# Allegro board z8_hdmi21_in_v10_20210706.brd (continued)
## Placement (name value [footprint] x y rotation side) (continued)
R275  49.9R  [R0402]  21.59 35.12 180 top
R276  49.9R  [R0402]  21.59 33.59 180 top
R277  49.9R  [R0402]  24.51 33.46 180 top
R278  49.9R  [R0402]  24.51 31.94 180 top
R279  49.9R  [R0402]  21.59 31.81 180 top
R280  49.9R  [R0402]  21.59 30.29 180 top
R281  49.9R  [R0402]  24.51 30.16 180 top
R282  49.9R  [R0402]  24.51 28.64 180 top
R283  49.9K  [R0402]  168.02 27.37 90 top
R284  49.9K  [R0402]  208.28 27.37 270 top
R285  200K  [R0402]  209.42 27.37 270 top
R286  0R  [R0402]  35.05 25.97 180 top
R287  0R  [R0402]  37.47 25.97 0 top
R288  0R_NC  [R0402]  29.84 25.46 90 top
R289  0R_NC  [R0402]  30.99 25.46 90 top
R290  500K  [R0402]  33.27 25.46 270 top
R291  100K  [R0402]  168.02 24.96 90 top
R292  2K  [R0402]  46.99 24.57 270 top
R293  3  [R0402]  157.23 24.19 90 top
R294  0R_NC  [R0402]  35.56 24.19 270 top
R295  0R_NC  [R0402]  36.96 24.19 270 top
R296  47K  [R0402]  38.99 24.19 180 top
R297  47K  [R0402]  29.21 23.69 180 top
R298  47K  [R0402]  31.62 23.69 0 top
R299  47K  [R0402]  38.96 22.92 180 top
R300  2K  [R0402]  46.99 22.29 90 top
R301  0R  [R0402]  29.72 21.91 270 top
R302  0R  [R0402]  31.12 21.91 270 top
R303  200K  [R0402]  38.96 20.51 180 top
R304  147K  [R0402]  64.52 19.24 180 top
R305  100K  [R0402]  91.19 19.24 180 top
R306  20K  [R0402]  110.11 19.24 180 top
R307  200K  [R0402]  176.91 19.24 180 top
R308  20K  [R0402]  66.29 18.73 90 top
R309  49.9K  [R0402]  70.74 18.73 270 top
R310  100K  [R0402]  92.96 18.73 90 top
R311  49.9K  [R0402]  97.41 18.73 270 top
R312  28K  [R0402]  111.89 18.73 90 top
R313  49.9K  [R0402]  116.33 18.73 270 top
R314  100K  [R0402]  178.69 18.73 90 top
R315  49.9K  [R0402]  183.13 18.73 270 top
R316  300  [R0402]  14.99 17.34 180 top
R317  52.3K  [R0402]  70.74 16.45 270 top
R318  52.3K  [R0402]  97.41 16.45 270 top
R319  52.3K  [R0402]  116.33 16.45 270 top
R320  52.3K  [R0402]  183.13 16.45 270 top
R321  10K  [R0402]  68.96 15.94 180 top
R322  10K  [R0402]  95.63 15.94 180 top
R323  10K  [R0402]  114.55 15.94 180 top
R324  10K  [R0402]  181.36 15.94 180 top
R325  300  [R0402]  14.99 15.81 180 top
R326  300  [R0402]  14.99 11.11 180 top
R327  300  [R0402]  14.99 9.59 180 top
R328  1M  [R0402]  96.39 7.18 180 top
R329  1M  [R0402]  147.19 7.18 180 top
R330  1M  [R0402]  197.99 7.18 180 top
R335  1K-NC  [R0402]  44.96 149.8 0 bottom
R336  1K-NC  [R0402]  44.96 148.53 0 bottom
R337  1K-NC  [R0402]  44.96 147.39 0 bottom
R338  1K-NC  [R0402]  27.81 146.76 0 bottom
R339  1K  [R0402]  25.53 146.76 180 bottom
R340  1K-NC  [R0402]  44.96 146.12 0 bottom
R341  1K  [R0402]  27.81 145.49 0 bottom
R342  1K-NC  [R0402]  25.53 145.49 180 bottom
R343  10K-NC  [R0402]  44.96 144.85 0 bottom
R344  10K-NC  [R0402]  27.81 143.84 0 bottom
R345  1K-NC  [R0402]  25.53 143.84 180 bottom
R346  10K-NC  [R0402]  44.96 143.57 0 bottom
R347  10K-NC  [R0402]  27.81 142.57 0 bottom
R348  1K-NC  [R0402]  25.53 142.57 180 bottom
R349  10K  [R0402]  44.96 142.44 0 bottom
R350  1K  [R0402]  27.81 141.3 0 bottom
R351  1K-NC  [R0402]  25.53 141.3 180 bottom
R352  1K-NC  [R0402]  44.96 141.17 0 bottom
R353  50  [R0402]  142.49 140.78 270 bottom
R354  50  [R0402]  141.35 140.78 270 bottom
R355  50  [R0402]  140.21 140.78 270 bottom
R356  50  [R0402]  139.06 140.78 270 bottom
R357  50  [R0402]  137.92 140.78 270 bottom
R358  50  [R0402]  136.78 140.78 270 bottom
R359  50  [R0402]  135.64 140.78 270 bottom
R360  50  [R0402]  134.49 140.78 270 bottom
R361  50  [R0402]  133.35 140.78 270 bottom
R362  50  [R0402]  132.21 140.78 270 bottom
R363  50  [R0402]  131.06 140.78 270 bottom
R364  50  [R0402]  129.92 140.78 270 bottom
R365  50  [R0402]  128.78 140.78 270 bottom
R366  50  [R0402]  127.64 140.78 270 bottom
R367  1K-NC  [R0402]  44.96 140.03 0 bottom
R368  1K  [R0402]  27.81 140.03 0 bottom
R369  1K-NC  [R0402]  25.53 140.03 180 bottom
R370  1K-NC  [R0402]  44.96 138.76 0 bottom
R371  1K  [R0402]  27.81 138.76 0 bottom
R372  1K-NC  [R0402]  25.53 138.76 180 bottom
R373  1K-NC  [R0402]  44.96 137.61 0 bottom
R380  100  [R0402]  134.87 131.03 270 bottom
R381  65K_NC  [R0402]  38.86 118.55 270 bottom
R382  65K  [R0402]  37.97 116.52 180 bottom
R383  65K_NC  [R0402]  29.72 116.52 0 bottom
R384  65K  [R0402]  27.43 116.52 0 bottom
R385  0R-NC  [R0402]  27.3 115.38 180 bottom
R386  0R  [R0402]  40.01 114.62 270 bottom
R387  0R-NC  [R0402]  38.86 114.62 270 bottom
R388  0R-NC  [R0402]  27.3 114.24 180 bottom
R389  65K_NC  [R0402]  37.21 113.22 90 bottom
R390  50  [R0402]  181.74 112.97 180 bottom
R391  65K_NC  [R0402]  39.5 112.71 180 bottom
R392  65K_NC  [R0402]  29.72 111.95 0 bottom
R393  65K_NC  [R0402]  27.3 111.95 0 bottom
R394  50  [R0402]  181.74 111.82 180 bottom
R395  50  [R0402]  181.74 110.68 180 bottom
R396  2K  [C0402-8]  121.88 109.62 0 bottom
R397  50  [R0402]  181.74 109.54 180 bottom
R398  10K  [C0402-8]  138.88 108.62 180 bottom
R399  50  [R0402]  181.74 108.39 180 bottom
R400  1K  [R0402]  140.59 108.14 90 bottom
R401  10K  [C0402-8]  138.88 107.62 180 bottom
R402  50  [R0402]  181.74 107.25 180 bottom
R403  240  [C0402-8]  144.39 106.12 90 bottom
R404  50  [R0402]  181.74 106.11 180 bottom
R405  100  [R0402]  171.98 105.6 180 bottom
R406  10K  [R0402]  145.54 143.95 90 bottom
R407  50  [R0402]  181.74 104.97 180 bottom
R408  4.7K/NC  [R0402]  132.08 104.97 270 bottom
R409  4.7K  [R0402]  130.94 104.97 270 bottom
R410  0-NC  [R0402]  136.91 104.46 90 bottom
R411  50  [R0402]  181.74 103.82 180 bottom
R412  0  [R0402]  135.76 103.7 90 bottom
R413  0  [C0402-8]  138.88 103.62 180 bottom
R414  0  [C0402-8]  140.39 103.12 90 bottom
R415  50  [R0402]  181.74 102.68 180 bottom
R416  4.7K/NC  [R0402]  132.08 102.68 90 bottom
R417  4.7K  [R0402]  130.94 102.68 90 bottom
R418  1K  [C0402-8]  137.89 102.62 180 bottom
R419  50  [R0402]  181.74 101.54 180 bottom
R420  10K  [C0402-8]  138.39 101.12 270 bottom
R421  0  [R0402]  134.75 100.9 0 bottom
R422  1K-NC  [R0402]  132.46 100.9 180 bottom
R423  50  [R0402]  181.74 100.39 180 bottom
R424  50  [R0402]  181.74 99.25 180 bottom
R425  0-NC  [C0402-8]  135.39 99.12 90 bottom
R426  50  [R0402]  181.74 98.11 180 bottom
R427  10K  [C0402-8]  122.89 96.62 0 bottom
R428  50  [R0402]  181.74 96.33 180 bottom
R429  0-NC  [C0402-8]  132.39 96.12 90 bottom
R430  50  [R0402]  181.74 95.19 180 bottom
R431  50  [R0402]  181.74 94.04 180 bottom
R432  50  [R0402]  181.74 92.9 180 bottom
R433  50  [R0402]  181.74 91.76 180 bottom
R434  10K  [C0402-8]  122.89 91.62 0 bottom
R435  50  [R0402]  181.74 90.61 180 bottom
R436  65K_NC  [R0402]  38.86 90.61 270 bottom
R437  100  [R0402]  171.98 89.85 180 bottom
R438  50  [R0402]  181.74 89.47 180 bottom
R439  65K  [R0402]  37.97 88.58 180 bottom
R440  65K_NC  [R0402]  29.72 88.58 0 bottom
R441  65K  [R0402]  27.43 88.58 0 bottom
R442  50  [R0402]  181.74 88.33 180 bottom
R443  10K  [C0402-8]  123.89 87.62 180 bottom
R444  0R-NC  [R0402]  27.3 87.44 180 bottom
R445  50  [R0402]  181.74 87.19 180 bottom
R446  0R  [R0402]  40.01 86.68 270 bottom
R447  0R-NC  [R0402]  38.86 86.68 270 bottom
R448  0R-NC  [R0402]  27.3 86.3 180 bottom
R449  50  [R0402]  181.74 86.04 180 bottom
R450  65K_NC  [R0402]  37.21 85.28 90 bottom
R451  50  [R0402]  181.74 84.9 180 bottom
R452  65K_NC  [R0402]  39.5 84.77 180 bottom
R453  240  [C0402-8]  143.39 84.11 270 bottom
R454  65K_NC  [R0402]  29.72 84.01 0 bottom
R455  65K_NC  [R0402]  27.43 84.01 0 bottom
R456  50  [R0402]  181.74 83.76 180 bottom
R457  240  [C0402-8]  125.39 83.13 90 bottom
R458  50  [R0402]  181.74 82.61 180 bottom
R459  50  [R0402]  181.74 81.47 180 bottom
R460  0  [C0402-8]  138.39 77.13 90 bottom
R461  2K  [C0402-8]  122.84 76.61 180 bottom
R462  65K_NC  [R0402]  38.86 62.67 270 bottom
R463  65K  [R0402]  37.97 60.64 180 bottom
R464  65K_NC  [R0402]  29.72 60.64 0 bottom
R465  65K  [R0402]  27.43 60.64 0 bottom
R466  0R-NC  [R0402]  27.3 59.5 180 bottom
R467  0R  [R0402]  40.01 58.74 270 bottom
R468  0R-NC  [R0402]  38.86 58.74 270 bottom
R469  0R-NC  [R0402]  27.3 58.36 180 bottom
R470  65K_NC  [R0402]  37.21 57.34 90 bottom
R471  65K_NC  [R0402]  39.5 56.83 180 bottom
R472  65K_NC  [R0402]  29.72 56.07 0 bottom
R473  65K_NC  [R0402]  27.3 56.07 0 bottom
R474  10K  [R0402]  219.96 51.5 0 bottom
R475  65K_NC  [R0402]  38.86 34.73 270 bottom
R476  65K  [R0402]  37.97 32.7 180 bottom
R477  65K_NC  [R0402]  29.72 32.7 0 bottom
R478  65K  [R0402]  27.43 32.7 0 bottom
R479  0R-NC  [R0402]  27.3 31.56 180 bottom
R480  0R  [R0402]  40.01 30.8 270 bottom
R481  0R-NC  [R0402]  38.86 30.8 270 bottom
R482  0R-NC  [R0402]  27.3 30.42 180 bottom
R483  14.7K  [R0402]  166.75 29.53 180 bottom
R484  65K_NC  [R0402]  37.21 29.4 90 bottom
R485  65K_NC  [R0402]  39.5 28.89 180 bottom
R486  65K_NC  [R0402]  29.72 28.13 0 bottom
R487  65K_NC  [R0402]  27.3 28.13 0 bottom
R488  100K  [R0402]  166.75 27.75 180 bottom
R489  2  [R0402]  164.97 26.48 270 bottom
R490  200K  [R0402]  169.55 20.38 90 bottom
R491  147K  [R0402]  168.4 20.38 90 bottom
R492  187K-NC  [R0402]  166.75 20.38 90 bottom
R493  0-NC  [R0402]  166.75 18.1 270 bottom
R691  22R  [R0402]  215.16 56.5 270 top
R693  22R  [R0402]  214.02 56.5 270 top
R694  22R  [R0402]  211.73 56.5 270 top
R695  22R  [R0402]  212.88 56.5 270 top
R696  22R  [R0402]  214.5 42.61 90 top
R697  22R  [R0402]  216.84 42.58 90 top
R698  22R  [R0402]  215.67 42.58 90 top
R699  22R  [R0402]  148.08 143.95 90 bottom
R700  22R  [R0402]  149.48 143.95 90 bottom
R701  22R  [R0402]  150.88 143.95 90 bottom
R702  22R  [R0402]  146.81 143.95 90 bottom
R703  22R  [R0402]  150.5 138.37 270 bottom
R704  22R  [R0402]  147.96 138.37 270 bottom
R705  22R  [R0402]  149.35 138.37 270 bottom
R706  22R  [R0402]  146.56 138.37 270 bottom
R707  22  [R0402]  151.64 138.37 90 bottom
R708  22R  [R0402]  245.8 153.94 0 top
R709  22R  [R0402]  245.79 152.75 0 top
R710  22R  [R0402]  245.84 151.6 0 top
R711  22R  [R0402]  245.89 136.85 0 top
R712  22R  [R0402]  245.91 138.07 0 top
R713  22R  [R0402]  245.87 134.46 0 top
R714  22R  [R0402]  245.88 135.58 0 top
U1  LED_DUAL_GREENCOLOR  [LED-4P]  5.46 163.05 270 top
U2  PCA9306DC1 A  [SOIC8_E0D65_4D55XE3D15]  26.22 151.22 180 top
U3  SP3012-04UTG  [UDFN-10]  16.74 149.75 90 top
U4  SP3012-04UTG  [UDFN-10]  16.74 145.09 90 top
U5  -  [TPS51200]  117.73 143.45 90 top
U6  MT25QU256ABA8E12-1SIT TR  [T-PBGA24-BALL]  154.26 141.81 90 top
U7  SP3012-04UTG  [UDFN-10]  16.74 140.65 90 top
U8  DDR3-1Gbit  [FBGA96-10X14]  171.58 135.83 90 top
U9  -  [TPS568215]  204.22 133.54 270 top
U10  DDR3-1Gbit  [FBGA96-10X14]  104.65 130.62 180 top
U11  DDR3-1Gbit  [FBGA96-10X14]  119.89 130.62 180 top
U12  DDR3-1Gbit  [FBGA96-10X14]  135.13 130.62 180 top
U13  SY6280AAC-NC  [SOT_23_5]  22.32 127.57 90 top
U14  -  [TPS51200]  184.4 122.62 0 top
U15  SP3012-04UTG  [UDFN-10]  16.74 120.03 90 top
U16  DDR3-1Gbit  [FBGA96-10X14]  171.58 120.59 90 top
U17  SP3012-04UTG  [UDFN-10]  16.74 116.52 90 top
U19  TMDS171RGZ  [QFN48_TMDS181]  33.37 115.5 180 top
U20  SP3012-04UTG  [UDFN-10]  16.74 113.09 90 top
U21  PCA9306DC1 A  [SOIC8_E0D65_4D55XE3D15]  43.28 106.61 180 top
U22  DDR3-1Gbit  [FBGA96-10X14]  171.58 105.35 90 top
U23  SY6280AAC-NC  [SOT_23_5]  22.32 99.63 90 top
U24  SP3012-04UTG  [UDFN-10]  16.74 92.09 90 top
U25  -  [TPS568215]  204.22 91.63 270 top
U26  Si5338A-CUSTOM  [QFN24]  85.6 91.38 180 top
U27  SP3012-04UTG  [UDFN-10]  16.74 88.58 90 top
U28  DDR3-1Gbit  [FBGA96-10X14]  171.58 88.84 90 top
U29  TMDS171RGZ  [QFN48_TMDS181]  33.37 87.56 180 top
U30  SP3012-04UTG  [UDFN-10]  16.74 85.15 90 top
U31  PCA9306DC1 A  [SOIC8_E0D65_4D55XE3D15]  43.28 78.67 180 top
U32  DDR3-1Gbit  [FBGA96-10X14]  171.58 73.6 90 top
U33  SY6280AAC-NC  [SOT_23_5]  22.32 71.69 90 top
U34  -  [TPS51200]  182.25 71.31 180 top
U35  SP3012-04UTG  [UDFN-10]  16.74 64.15 90 top
U36  SP3012-04UTG  [UDFN-10]  16.74 60.64 90 top
U37  TMDS171RGZ  [QFN48_TMDS181]  33.37 59.62 180 top
U38  W25Q16CLSNIG  [SOIC8W]  228.52 58.36 180 top
U39  Si5338A-CUSTOM  [QFN24]  135.25 58.61 90 top
U40  DDR3-1Gbit  [FBGA96-10X14]  171.58 58.36 90 top
U41  SP3012-04UTG  [UDFN-10]  16.74 57.21 90 top
U42  PCA9306DC1 A  [SOIC8_E0D65_4D55XE3D15]  43.28 50.73 180 top
U43  STM32F030CX  [LQFP48]  218.82 49.72 90 top
U44  SY6280AAC-NC  [SOT_23_5]  22.32 43.75 90 top
U45  TLV62569  [SOT23-5]  83.31 41.34 90 top
U46  SP3012-04UTG  [UDFN-10]  16.74 36.21 90 top
U47  SP3012-04UTG  [UDFN-10]  16.74 32.7 90 top
U48  TMDS171RGZ  [QFN48_TMDS181]  33.37 31.68 180 top
U49  SP3012-04UTG  [UDFN-10]  16.74 29.27 90 top
U50  TLV62569  [SOT23-5]  205.87 28.26 180 top
U51  -  [TPS568215]  68.58 23.05 180 top
U52  -  [TPS568215]  95.25 23.05 180 top
U53  -  [TPS568215]  114.17 23.05 180 top
U54  -  [TPS568215]  180.97 23.05 180 top
U55  PCA9306DC1 A  [SOIC8_E0D65_4D55XE3D15]  43.28 22.79 180 top
U56  TPS53355  [DQP_N22]  163.58 22.29 270 top
U57  LED_DUAL_GREENCOLOR  [LED-4P]  5.46 14.5 270 top
U58  LED_DUAL_GREENCOLOR  [LED-4P]  5.46 8.28 270 top
U59  -  [DS125MB203]  36.58 143.2 270 bottom
Y1  25MHz(3225)-3.3V-NC  [XTAL_ABM8]  92.71 95.95 90 top
Y2  CRYSTAL_4pin_3225_25MHz  [XTAL_ABM8]  92.46 89.34 270 top
Y3  25MHz(3225)-3.3V-NC  [XTAL_ABM8]  138.81 51.63 0 top
Y4  CRYSTAL_4pin_3225_25MHz  [XTAL_ABM8]  132.08 51.37 180 top
Y5  CRYSTAL_4pin_3225_25MHz  [XTAL_ABM8]  227.33 49.34 270 top

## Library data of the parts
C1-C3 C43 C143 C214 C274 C338 C387-C389 = CAP NP: Tolerance: RichardLC; User Part Number: pn; room: DVI
C4-C6 C8 C11 C12 C15 C18 C20 C21 C31 C35-C42 C44-C46 C50-C55 C59-C66 C77-C79 C81-C87 C91 C96-C101 C103-C105 C107-C110 C113 C115 C117 C120 C122 C130 C132 C133 C135 C138 C141 C142 C144 C146 C164 C166 C169 C171 C173 C175 C178 C181 C185 C187 C188 C191 C194 C199 C202 C212 C216 C219 C222 C223 C226 C239 C241-C243 C245 C252 C254 C255 C257 C260 C263 C265 C266 C269 C272 C273 C275-C278 C280 C282 C285 C295 C296 C300-C302 C331-C333 C335 C341 C342 C347 C348 C353 C354 C359 C360 C364 C369 C372 C375 C378 C381 C396 C397 C402 C403 C405 C407 C409 C412 C414 C415 C510 C511 C537 C539 C541 C587 C589 C590 C596 C597 C599 C601 C603 C605 C607-C610 C612-C615 C617 C619 C621 C626 C628 C630 C631 = CAP NP: Tolerance: RichardLC; User Part Number: pn; signal model: C0402_0.1UF
C7 C145 C148 C179 C211 C227 C303-C307 = CAP POL
C9 C13 C22 C24-C27 C32 C49 C56-C58 C74 C95 C118 C123 C131 C140 C147 C177 C183 C190 C198 C205 C213 C221 C224 C230 C253 C334 C336 C370 C371 C373 C374 C376 C377 C379 C380 C382-C386 C404 C406 C408 C411 C413 C536 C538 C540 C586 C588 C598 C600 C602 C604 C606 C616 C618 C620 C622 C627 C629 C704 = CAP NP: Tolerance: RichardLC; User Part Number: pn
C10 C14 C16 C17 C19 C67-C73 C80 C90 C92-C94 C124-C129 C134 C136 C137 C139 C149-C154 C165 C167 C168 C170 C203 C206-C210 C215 C217 C218 C220 C228 C231-C238 C240 C244 C279 C394 C395 C410 C417 C427 C459 C487 C531 C580 C593 = CAP NP: User Part Number: pn; Tolerance: RichardLC; signal model: C0402_0.1UF
C23 C28-C30 C33 C34 C76 C89 C102 C106 C111 C114 C155-C158 C163 C193 C201 C204 C225 C229 C283 C286-C294 C297-C299 C308-C312 C315-C317 C320-C326 C329 C330 C337 C339 C340 C343-C346 C349-C352 C355-C358 C361-C363 C611 C623-C625 C700 C701 = CAP NP: User Part Number: pn; Tolerance: RichardLC
C75 C88 C192 C200 C313 C314 C318 C319 C327 C328 C421 C430 C438 C441 C458 C467 C477 C512 C530 C553 C576 C591 C632 C702 C703 = CAP NP
C159-C162 C172 C174 C176 C180 C184 C186 C195-C197 C246-C251 C256 C259 C262 C268 = CAP: Tolerance: RichardLC; User Part Number: pn
C182 C189 C270 C271 C281 C284 = CAP_0402_100pF_COG_50V: Tolerance: RichardLC; User Part Number: pn
C258 C261 C264 C267 = CAP: User Part Number: pn; Tolerance: RichardLC
C365-C368 = CAPACITOR NON-POL: User Part Number: pn; Tolerance: RichardLC
C390-C393 C398-C401 C423 C425 C426 C428 C429 C432-C434 C436 C437 C439 C440 C442-C457 C460-C466 C468-C476 C478-C486 C488-C509 C513-C529 C532-C535 C542-C552 C554-C575 C577-C579 C581-C585 C592 C594 C595 C661-C668 = CAP NP: signal model: C0402_0.1UF-1
D1-D4 = DIODE_0
FAN1 FAN2 = CONN FLEX 5_0
HDMI1 J6 J8 J10 J14 = CONN_HDMI_1: Tolerance: TOL; User Part Number: PART#
J1-J3 J16-J18 = MECHANICAL_HOLE_0
J4 = CONN SOCKET 5x2
J5 J7 J9 J12 = CON2
J11 = CON7
J13 JA1 = 4 HEADER
J15 = 4 HEADER_0
JT1 = ERmetZD-MV-973080_1
L1 L8 L9 R179-R192 R396 R398 R401 R403 R413 R414 R418 R420 R425 R427 R429 R434 R443 R453 R457 R460 R461 = R
L2 L4 L7 L10-L19 L21-L24 L34 L35 = L_0
L5 L6 L20 = L_0: User Part Number: pn; Tolerance: RichardLC
M1-M6 = MARK
P1 = 10AX027 F34_2
Q1-Q6 = MFE825_0
R1-R21 R24-R29 R39 R44-R58 R60 R63 R65-R75 R77 R78 R80 R82-R88 R90 R91 R93-R96 R98-R102 R104 R105 R107 R108 R110 R114-R117 R120 R122-R132 R135-R138 R140 R142 R144 R146 R147 R149-R151 R153 R155 R158-R167 R169-R178 R193 R194 R196 R199-R211 R213-R221 R223-R227 R230-R245 R247 R248 R250-R330 R335-R352 R367-R373 R381-R389 R391-R393 R400 R406 R408 R409 R416 R417 R436 R439-R441 R444 R446-R448 R450 R452 R454 R455 R462-R492 R691 R693-R714 = R: User Part Number: pn; Tolerance: RichardLC
R22 R23 R38 R40-R43 R59 R61 R62 R64 R76 R89 R121 R168 R195 R197 R198 R212 R249 R410 R412 R421 R422 R493 = R: Tolerance: RichardLC; User Part Number: pn
R30-R33 R361-R366 = R: Tolerance: RichardLC; User Part Number: pn; signal model: R_R0402_50
R34-R37 R92 R97 R103 R106 R109 R111-R113 R139 R141 R143 R145 R148 R152 R156 R157 R353-R360 R390 R394 R395 R397 R399 R402 R404 R407 R411 R415 R419 R423 R424 R426 R428 R430-R433 R435 R438 R442 R445 R449 R451 R456 R458 R459 = R: User Part Number: pn; Tolerance: RichardLC; signal model: R_R0402_50
R118 R119 R133 R134 R154 R222 R228 R229 R246 = RESISTOR: User Part Number: pn; Tolerance: RichardLC
R380 R437 = R: User Part Number: pn; Tolerance: RichardLC; signal model: R_R0402_100
R405 = R: Tolerance: RichardLC; User Part Number: pn; signal model: R_R0402_100
U1 U57 U58 = LED_DUAL_BICOLOR
U2 U21 U31 U42 U55 = PCA9306DC1 A
U3 U4 U7 U15 U17 U20 U24 U27 U30 U35 U36 U41 U46 U47 U49 = SP3012-04UTG
U5 U9 U14 U25 U34 U51-U54 = TPS54040_0
U6 = EPCQL_0
U8 U10-U12 U16 U22 U28 U32 U40 = DDR3-512MB
U13 U23 U33 U44 = SWITCH_SY6280
U19 U29 U37 U48 = DP159RGZ_0
U26 U39 = Si5338A_0: User Part Number: *
U38 = EPCS1/4
U43 = STM32F051CX
U45 U50 = TLV62565_0
U56 = TPS53355
U59 = DS125MB203_0
Y1 Y3 = OSC4/SM_0
Y2 Y4 Y5 = CRYSTAL_4pin_3225

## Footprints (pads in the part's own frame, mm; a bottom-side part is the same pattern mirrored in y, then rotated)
3PIN_POWER
  oval 3.3x1.3 hole 2.7x0.7: 1(0,-6.6) 3(0,0)
  oval 1.3x3.3 hole 0.7x2.7: 2(-3.8,-2.8)
BGA1152_PAD18
  round 0.457 smd: A2(-15.5,16.5) A3(-14.5,16.5) A4(-13.5,16.5) A5(-12.5,16.5) A6(-11.5,16.5) A7(-10.5,16.5) A8(-9.5,16.5) A9(-8.5,16.5) A10(-7.5,16.5) A11(-6.5,16.5) A12(-5.5,16.5) A13(-4.5,16.5) A14(-3.5,16.5) A15(-2.5,16.5) A16(-1.5,16.5) A17(-0.5,16.5) A18(0.5,16.5) A19(1.5,16.5) A20(2.5,16.5) A21(3.5,16.5) A22(4.5,16.5) A23(5.5,16.5) A24(6.5,16.5) A25(7.5,16.5) A26(8.5,16.5) A27(9.5,16.5) A28(10.5,16.5) A29(11.5,16.5) A30(12.5,16.5) A31(13.5,16.5) A32(14.5,16.5) A33(15.5,16.5) AA1(-16.5,-3.5) AA2(-15.5,-3.5) AA3(-14.5,-3.5) AA4(-13.5,-3.5) AA5(-12.5,-3.5) AA6(-11.5,-3.5) AA7(-10.5,-3.5) AA8(-9.5,-3.5) AA9(-8.5,-3.5) AA10(-7.5,-3.5) AA11(-6.5,-3.5) AA12(-5.5,-3.5) AA13(-4.5,-3.5) AA14(-3.5,-3.5) AA15(-2.5,-3.5) AA16(-1.5,-3.5) AA17(-0.5,-3.5) AA18(0.5,-3.5) AA19(1.5,-3.5) AA20(2.5,-3.5) AA21(3.5,-3.5) AA22(4.5,-3.5) AA23(5.5,-3.5) AA24(6.5,-3.5) AA25(7.5,-3.5) AA26(8.5,-3.5) AA27(9.5,-3.5) AA28(10.5,-3.5) AA29(11.5,-3.5) AA30(12.5,-3.5) AA31(13.5,-3.5) AA32(14.5,-3.5) AA33(15.5,-3.5) AA34(16.5,-3.5) AB1(-16.5,-4.5) AB2(-15.5,-4.5) AB3(-14.5,-4.5) AB4(-13.5,-4.5) AB5(-12.5,-4.5) AB6(-11.5,-4.5) AB7(-10.5,-4.5) AB8(-9.5,-4.5) AB9(-8.5,-4.5) AB10(-7.5,-4.5) AB11(-6.5,-4.5) AB12(-5.5,-4.5) AB13(-4.5,-4.5) AB14(-3.5,-4.5) AB15(-2.5,-4.5) AB16(-1.5,-4.5) AB17(-0.5,-4.5) AB18(0.5,-4.5) AB19(1.5,-4.5) AB20(2.5,-4.5) AB21(3.5,-4.5) AB22(4.5,-4.5) AB23(5.5,-4.5) AB24(6.5,-4.5) AB25(7.5,-4.5) AB26(8.5,-4.5) AB27(9.5,-4.5) AB28(10.5,-4.5) AB29(11.5,-4.5) AB30(12.5,-4.5) AB31(13.5,-4.5) AB32(14.5,-4.5) AB33(15.5,-4.5) AB34(16.5,-4.5) AC1(-16.5,-5.5) AC2(-15.5,-5.5) AC3(-14.5,-5.5) AC4(-13.5,-5.5) AC5(-12.5,-5.5) AC6(-11.5,-5.5) AC7(-10.5,-5.5) AC8(-9.5,-5.5) AC9(-8.5,-5.5) AC10(-7.5,-5.5) AC11(-6.5,-5.5) AC12(-5.5,-5.5) AC13(-4.5,-5.5) AC14(-3.5,-5.5) AC15(-2.5,-5.5) AC16(-1.5,-5.5) AC17(-0.5,-5.5) AC18(0.5,-5.5) AC19(1.5,-5.5) AC20(2.5,-5.5) AC21(3.5,-5.5) AC22(4.5,-5.5) AC23(5.5,-5.5) AC24(6.5,-5.5) AC25(7.5,-5.5) AC26(8.5,-5.5) AC27(9.5,-5.5) AC28(10.5,-5.5) AC29(11.5,-5.5) AC30(12.5,-5.5) AC31(13.5,-5.5) AC32(14.5,-5.5) AC33(15.5,-5.5) AC34(16.5,-5.5) AD1(-16.5,-6.5) AD2(-15.5,-6.5) AD3(-14.5,-6.5) AD4(-13.5,-6.5) AD5(-12.5,-6.5) AD6(-11.5,-6.5) AD7(-10.5,-6.5) AD8(-9.5,-6.5) AD9(-8.5,-6.5) AD10(-7.5,-6.5) AD11(-6.5,-6.5) AD12(-5.5,-6.5) AD13(-4.5,-6.5) AD14(-3.5,-6.5) AD15(-2.5,-6.5) AD16(-1.5,-6.5) AD17(-0.5,-6.5) AD18(0.5,-6.5) AD19(1.5,-6.5) AD20(2.5,-6.5) AD21(3.5,-6.5) AD22(4.5,-6.5) AD23(5.5,-6.5) AD24(6.5,-6.5) AD25(7.5,-6.5) AD26(8.5,-6.5) AD27(9.5,-6.5) AD28(10.5,-6.5) AD29(11.5,-6.5) AD30(12.5,-6.5) AD31(13.5,-6.5) AD32(14.5,-6.5) AD33(15.5,-6.5) AD34(16.5,-6.5) AE1(-16.5,-7.5) AE2(-15.5,-7.5) AE3(-14.5,-7.5) AE4(-13.5,-7.5) AE5(-12.5,-7.5) AE6(-11.5,-7.5) AE7(-10.5,-7.5) AE8(-9.5,-7.5) AE9(-8.5,-7.5) AE10(-7.5,-7.5) AE11(-6.5,-7.5) AE12(-5.5,-7.5) AE13(-4.5,-7.5) AE14(-3.5,-7.5) AE15(-2.5,-7.5) AE16(-1.5,-7.5) AE17(-0.5,-7.5) AE18(0.5,-7.5) AE19(1.5,-7.5) AE20(2.5,-7.5) AE21(3.5,-7.5) AE22(4.5,-7.5) AE23(5.5,-7.5) AE24(6.5,-7.5) AE25(7.5,-7.5) AE26(8.5,-7.5) AE27(9.5,-7.5) AE28(10.5,-7.5) AE29(11.5,-7.5) AE30(12.5,-7.5) AE31(13.5,-7.5) AE32(14.5,-7.5) AE33(15.5,-7.5) AE34(16.5,-7.5) AF1(-16.5,-8.5) AF2(-15.5,-8.5) AF3(-14.5,-8.5) AF4(-13.5,-8.5) AF5(-12.5,-8.5) AF6(-11.5,-8.5) AF7(-10.5,-8.5) AF8(-9.5,-8.5) AF9(-8.5,-8.5) AF10(-7.5,-8.5) AF11(-6.5,-8.5) AF12(-5.5,-8.5) AF13(-4.5,-8.5) AF14(-3.5,-8.5) AF15(-2.5,-8.5) AF16(-1.5,-8.5) AF17(-0.5,-8.5) AF18(0.5,-8.5) AF19(1.5,-8.5) AF20(2.5,-8.5) AF21(3.5,-8.5) AF22(4.5,-8.5) AF23(5.5,-8.5) AF24(6.5,-8.5) AF25(7.5,-8.5) AF26(8.5,-8.5) AF27(9.5,-8.5) AF28(10.5,-8.5) AF29(11.5,-8.5) AF30(12.5,-8.5) AF31(13.5,-8.5) AF32(14.5,-8.5) AF33(15.5,-8.5) AF34(16.5,-8.5) AG1(-16.5,-9.5) AG2(-15.5,-9.5) AG3(-14.5,-9.5) AG4(-13.5,-9.5) AG5(-12.5,-9.5) AG6(-11.5,-9.5) AG7(-10.5,-9.5) AG8(-9.5,-9.5) AG9(-8.5,-9.5) AG10(-7.5,-9.5) AG11(-6.5,-9.5) AG12(-5.5,-9.5) AG13(-4.5,-9.5) AG14(-3.5,-9.5) AG15(-2.5,-9.5) AG16(-1.5,-9.5) AG17(-0.5,-9.5) AG18(0.5,-9.5) AG19(1.5,-9.5) AG20(2.5,-9.5) AG21(3.5,-9.5) AG22(4.5,-9.5) AG23(5.5,-9.5) AG24(6.5,-9.5) AG25(7.5,-9.5) AG26(8.5,-9.5) AG27(9.5,-9.5) AG28(10.5,-9.5) AG29(11.5,-9.5) AG30(12.5,-9.5) AG31(13.5,-9.5) AG32(14.5,-9.5) AG33(15.5,-9.5) AG34(16.5,-9.5) AH1(-16.5,-10.5) AH2(-15.5,-10.5) AH3(-14.5,-10.5) AH4(-13.5,-10.5) AH5(-12.5,-10.5) AH6(-11.5,-10.5) AH7(-10.5,-10.5) AH8(-9.5,-10.5) AH9(-8.5,-10.5) AH10(-7.5,-10.5) AH11(-6.5,-10.5) AH12(-5.5,-10.5) AH13(-4.5,-10.5) AH14(-3.5,-10.5) AH15(-2.5,-10.5) AH16(-1.5,-10.5) AH17(-0.5,-10.5) AH18(0.5,-10.5) AH19(1.5,-10.5) AH20(2.5,-10.5) AH21(3.5,-10.5) AH22(4.5,-10.5) AH23(5.5,-10.5) AH24(6.5,-10.5) AH25(7.5,-10.5) AH26(8.5,-10.5) AH27(9.5,-10.5) AH28(10.5,-10.5) AH29(11.5,-10.5) AH30(12.5,-10.5) AH31(13.5,-10.5) AH32(14.5,-10.5) AH33(15.5,-10.5) AH34(16.5,-10.5) AJ1(-16.5,-11.5) AJ2(-15.5,-11.5) AJ3(-14.5,-11.5) AJ4(-13.5,-11.5) AJ5(-12.5,-11.5) AJ6(-11.5,-11.5) AJ7(-10.5,-11.5) AJ8(-9.5,-11.5) AJ9(-8.5,-11.5) AJ10(-7.5,-11.5) AJ11(-6.5,-11.5) AJ12(-5.5,-11.5) AJ13(-4.5,-11.5) AJ14(-3.5,-11.5) AJ15(-2.5,-11.5) AJ16(-1.5,-11.5) AJ17(-0.5,-11.5) AJ18(0.5,-11.5) AJ19(1.5,-11.5) AJ20(2.5,-11.5) AJ21(3.5,-11.5) AJ22(4.5,-11.5) AJ23(5.5,-11.5) AJ24(6.5,-11.5) AJ25(7.5,-11.5) AJ26(8.5,-11.5) AJ27(9.5,-11.5) AJ28(10.5,-11.5) AJ29(11.5,-11.5) AJ30(12.5,-11.5) AJ31(13.5,-11.5) AJ32(14.5,-11.5) AJ33(15.5,-11.5) AJ34(16.5,-11.5) AK1(-16.5,-12.5) AK2(-15.5,-12.5) AK3(-14.5,-12.5) AK4(-13.5,-12.5) AK5(-12.5,-12.5) AK6(-11.5,-12.5) AK7(-10.5,-12.5) AK8(-9.5,-12.5) AK9(-8.5,-12.5) AK10(-7.5,-12.5) AK11(-6.5,-12.5) AK12(-5.5,-12.5) AK13(-4.5,-12.5) AK14(-3.5,-12.5) AK15(-2.5,-12.5) AK16(-1.5,-12.5) AK17(-0.5,-12.5) AK18(0.5,-12.5) AK19(1.5,-12.5) AK20(2.5,-12.5) AK21(3.5,-12.5) AK22(4.5,-12.5) AK23(5.5,-12.5) AK24(6.5,-12.5) AK25(7.5,-12.5) AK26(8.5,-12.5) AK27(9.5,-12.5) AK28(10.5,-12.5) AK29(11.5,-12.5) AK30(12.5,-12.5) AK31(13.5,-12.5) AK32(14.5,-12.5) AK33(15.5,-12.5) AK34(16.5,-12.5) AL1(-16.5,-13.5) AL2(-15.5,-13.5) AL3(-14.5,-13.5) AL4(-13.5,-13.5) AL5(-12.5,-13.5) AL6(-11.5,-13.5) AL7(-10.5,-13.5) AL8(-9.5,-13.5) AL9(-8.5,-13.5) AL10(-7.5,-13.5) AL11(-6.5,-13.5) AL12(-5.5,-13.5) AL13(-4.5,-13.5) AL14(-3.5,-13.5) AL15(-2.5,-13.5) AL16(-1.5,-13.5) AL17(-0.5,-13.5) AL18(0.5,-13.5) AL19(1.5,-13.5) AL20(2.5,-13.5) AL21(3.5,-13.5) AL22(4.5,-13.5) AL23(5.5,-13.5) AL24(6.5,-13.5) AL25(7.5,-13.5) AL26(8.5,-13.5) AL27(9.5,-13.5) AL28(10.5,-13.5) AL29(11.5,-13.5) AL30(12.5,-13.5) AL31(13.5,-13.5) AL32(14.5,-13.5) AL33(15.5,-13.5) AL34(16.5,-13.5) AM1(-16.5,-14.5) AM2(-15.5,-14.5) AM3(-14.5,-14.5) AM4(-13.5,-14.5) AM5(-12.5,-14.5) AM6(-11.5,-14.5) AM7(-10.5,-14.5) AM8(-9.5,-14.5) AM9(-8.5,-14.5) AM10(-7.5,-14.5) AM11(-6.5,-14.5) AM12(-5.5,-14.5) AM13(-4.5,-14.5) AM14(-3.5,-14.5) AM15(-2.5,-14.5) AM16(-1.5,-14.5) AM17(-0.5,-14.5) AM18(0.5,-14.5) AM19(1.5,-14.5) AM20(2.5,-14.5) AM21(3.5,-14.5) AM22(4.5,-14.5) AM23(5.5,-14.5) AM24(6.5,-14.5) AM25(7.5,-14.5) AM26(8.5,-14.5) AM27(9.5,-14.5) AM28(10.5,-14.5) AM29(11.5,-14.5) AM30(12.5,-14.5) AM31(13.5,-14.5) AM32(14.5,-14.5) AM33(15.5,-14.5) AM34(16.5,-14.5) AN1(-16.5,-15.5) AN2(-15.5,-15.5) AN3(-14.5,-15.5) AN4(-13.5,-15.5) AN5(-12.5,-15.5) AN6(-11.5,-15.5) AN7(-10.5,-15.5) AN8(-9.5,-15.5) AN9(-8.5,-15.5) AN10(-7.5,-15.5) AN11(-6.5,-15.5) AN12(-5.5,-15.5) AN13(-4.5,-15.5) AN14(-3.5,-15.5) AN15(-2.5,-15.5) AN16(-1.5,-15.5) AN17(-0.5,-15.5) AN18(0.5,-15.5) AN19(1.5,-15.5) AN20(2.5,-15.5) AN21(3.5,-15.5) AN22(4.5,-15.5) AN23(5.5,-15.5) AN24(6.5,-15.5) AN25(7.5,-15.5) AN26(8.5,-15.5) AN27(9.5,-15.5) AN28(10.5,-15.5) AN29(11.5,-15.5) AN30(12.5,-15.5) AN31(13.5,-15.5) AN32(14.5,-15.5) AN33(15.5,-15.5) AN34(16.5,-15.5) AP2(-15.5,-16.5) AP3(-14.5,-16.5) AP4(-13.5,-16.5) AP5(-12.5,-16.5) AP6(-11.5,-16.5) AP7(-10.5,-16.5) AP8(-9.5,-16.5) AP9(-8.5,-16.5) AP10(-7.5,-16.5) AP11(-6.5,-16.5) AP12(-5.5,-16.5) AP13(-4.5,-16.5) AP14(-3.5,-16.5) AP15(-2.5,-16.5) AP16(-1.5,-16.5) AP17(-0.5,-16.5) AP18(0.5,-16.5) AP19(1.5,-16.5) AP20(2.5,-16.5) AP21(3.5,-16.5) AP22(4.5,-16.5) AP23(5.5,-16.5) AP24(6.5,-16.5) AP25(7.5,-16.5) AP26(8.5,-16.5) AP27(9.5,-16.5) AP28(10.5,-16.5) AP29(11.5,-16.5) AP30(12.5,-16.5) AP31(13.5,-16.5) AP32(14.5,-16.5) AP33(15.5,-16.5) B1(-16.5,15.5) B2(-15.5,15.5) B3(-14.5,15.5) B4(-13.5,15.5) B5(-12.5,15.5) B6(-11.5,15.5) B7(-10.5,15.5) B8(-9.5,15.5) B9(-8.5,15.5) B10(-7.5,15.5) B11(-6.5,15.5) B12(-5.5,15.5) B13(-4.5,15.5) B14(-3.5,15.5) B15(-2.5,15.5) B16(-1.5,15.5) B17(-0.5,15.5) B18(0.5,15.5) B19(1.5,15.5) B20(2.5,15.5) B21(3.5,15.5) B22(4.5,15.5) B23(5.5,15.5) B24(6.5,15.5) B25(7.5,15.5) B26(8.5,15.5) B27(9.5,15.5) B28(10.5,15.5) B29(11.5,15.5) B30(12.5,15.5) B31(13.5,15.5) B32(14.5,15.5) B33(15.5,15.5) B34(16.5,15.5) C1(-16.5,14.5) C2(-15.5,14.5) C3(-14.5,14.5) C4(-13.5,14.5) C5(-12.5,14.5) C6(-11.5,14.5) C7(-10.5,14.5) C8(-9.5,14.5) C9(-8.5,14.5) C10(-7.5,14.5) C11(-6.5,14.5) C12(-5.5,14.5) C13(-4.5,14.5) C14(-3.5,14.5) C15(-2.5,14.5) C16(-1.5,14.5) C17(-0.5,14.5) C18(0.5,14.5) C19(1.5,14.5) C20(2.5,14.5) C21(3.5,14.5) C22(4.5,14.5) C23(5.5,14.5) C24(6.5,14.5) C25(7.5,14.5) C26(8.5,14.5) C27(9.5,14.5) C28(10.5,14.5) C29(11.5,14.5) C30(12.5,14.5) C31(13.5,14.5) C32(14.5,14.5) C33(15.5,14.5) C34(16.5,14.5) D1(-16.5,13.5) D2(-15.5,13.5) D3(-14.5,13.5) D4(-13.5,13.5) D5(-12.5,13.5) D6(-11.5,13.5) D7(-10.5,13.5) D8(-9.5,13.5) D9(-8.5,13.5) D10(-7.5,13.5) D11(-6.5,13.5) D12(-5.5,13.5) D13(-4.5,13.5) D14(-3.5,13.5) D15(-2.5,13.5) D16(-1.5,13.5) D17(-0.5,13.5) D18(0.5,13.5) D19(1.5,13.5) D20(2.5,13.5) D21(3.5,13.5) D22(4.5,13.5) D23(5.5,13.5) D24(6.5,13.5) D25(7.5,13.5) D26(8.5,13.5) D27(9.5,13.5) D28(10.5,13.5) D29(11.5,13.5) D30(12.5,13.5) D31(13.5,13.5) D32(14.5,13.5) D33(15.5,13.5) D34(16.5,13.5) E1(-16.5,12.5) E2(-15.5,12.5) E3(-14.5,12.5) E4(-13.5,12.5) E5(-12.5,12.5) E6(-11.5,12.5) E7(-10.5,12.5) E8(-9.5,12.5) E9(-8.5,12.5) E10(-7.5,12.5) E11(-6.5,12.5) E12(-5.5,12.5) E13(-4.5,12.5) E14(-3.5,12.5) E15(-2.5,12.5) E16(-1.5,12.5) E17(-0.5,12.5) E18(0.5,12.5) E19(1.5,12.5) E20(2.5,12.5) E21(3.5,12.5) E22(4.5,12.5) E23(5.5,12.5) E24(6.5,12.5) E25(7.5,12.5) E26(8.5,12.5) E27(9.5,12.5) E28(10.5,12.5) E29(11.5,12.5) E30(12.5,12.5) E31(13.5,12.5) E32(14.5,12.5) E33(15.5,12.5) E34(16.5,12.5) F1(-16.5,11.5) F2(-15.5,11.5) F3(-14.5,11.5) F4(-13.5,11.5) F5(-12.5,11.5) F6(-11.5,11.5) F7(-10.5,11.5) F8(-9.5,11.5) F9(-8.5,11.5) F10(-7.5,11.5) F11(-6.5,11.5) F12(-5.5,11.5) F13(-4.5,11.5) F14(-3.5,11.5) F15(-2.5,11.5) F16(-1.5,11.5) F17(-0.5,11.5) F18(0.5,11.5) F19(1.5,11.5) F20(2.5,11.5) F21(3.5,11.5) F22(4.5,11.5) F23(5.5,11.5) F24(6.5,11.5) F25(7.5,11.5) F26(8.5,11.5) F27(9.5,11.5) F28(10.5,11.5) F29(11.5,11.5) F30(12.5,11.5) F31(13.5,11.5) F32(14.5,11.5) F33(15.5,11.5) F34(16.5,11.5) G1(-16.5,10.5) G2(-15.5,10.5) G3(-14.5,10.5) G4(-13.5,10.5) G5(-12.5,10.5) G6(-11.5,10.5) G7(-10.5,10.5) G8(-9.5,10.5) G9(-8.5,10.5) G10(-7.5,10.5) G11(-6.5,10.5) G12(-5.5,10.5) G13(-4.5,10.5) G14(-3.5,10.5) G15(-2.5,10.5) G16(-1.5,10.5) G17(-0.5,10.5) G18(0.5,10.5) G19(1.5,10.5) G20(2.5,10.5) G21(3.5,10.5) G22(4.5,10.5) G23(5.5,10.5) G24(6.5,10.5) G25(7.5,10.5) G26(8.5,10.5) G27(9.5,10.5) G28(10.5,10.5) G29(11.5,10.5) G30(12.5,10.5) G31(13.5,10.5) G32(14.5,10.5) G33(15.5,10.5) G34(16.5,10.5) H1(-16.5,9.5) H2(-15.5,9.5) H3(-14.5,9.5) H4(-13.5,9.5) H5(-12.5,9.5) H6(-11.5,9.5) H7(-10.5,9.5) H8(-9.5,9.5) H9(-8.5,9.5) H10(-7.5,9.5) H11(-6.5,9.5) H12(-5.5,9.5) H13(-4.5,9.5) H14(-3.5,9.5) H15(-2.5,9.5) H16(-1.5,9.5) H17(-0.5,9.5) H18(0.5,9.5) H19(1.5,9.5) H20(2.5,9.5) H21(3.5,9.5) H22(4.5,9.5) H23(5.5,9.5) H24(6.5,9.5) H25(7.5,9.5) H26(8.5,9.5) H27(9.5,9.5) H28(10.5,9.5) H29(11.5,9.5) H30(12.5,9.5) H31(13.5,9.5) H32(14.5,9.5) H33(15.5,9.5) H34(16.5,9.5) J1(-16.5,8.5) J2(-15.5,8.5) J3(-14.5,8.5) J4(-13.5,8.5) J5(-12.5,8.5) J6(-11.5,8.5) J7(-10.5,8.5) J8(-9.5,8.5) J9(-8.5,8.5) J10(-7.5,8.5) J11(-6.5,8.5) J12(-5.5,8.5) J13(-4.5,8.5) J14(-3.5,8.5) J15(-2.5,8.5) J16(-1.5,8.5) J17(-0.5,8.5) J18(0.5,8.5) J19(1.5,8.5) J20(2.5,8.5) J21(3.5,8.5) J22(4.5,8.5) J23(5.5,8.5) J24(6.5,8.5) J25(7.5,8.5) J26(8.5,8.5) J27(9.5,8.5) J28(10.5,8.5) J29(11.5,8.5) J30(12.5,8.5) J31(13.5,8.5) J32(14.5,8.5) J33(15.5,8.5) J34(16.5,8.5) K1(-16.5,7.5) K2(-15.5,7.5) K3(-14.5,7.5) K4(-13.5,7.5) K5(-12.5,7.5) K6(-11.5,7.5) K7(-10.5,7.5) K8(-9.5,7.5) K9(-8.5,7.5) K10(-7.5,7.5) K11(-6.5,7.5) K12(-5.5,7.5) K13(-4.5,7.5) K14(-3.5,7.5) K15(-2.5,7.5) K16(-1.5,7.5) K17(-0.5,7.5) K18(0.5,7.5) K19(1.5,7.5) K20(2.5,7.5) K21(3.5,7.5) K22(4.5,7.5) K23(5.5,7.5) K24(6.5,7.5) K25(7.5,7.5) K26(8.5,7.5) K27(9.5,7.5) K28(10.5,7.5) K29(11.5,7.5) K30(12.5,7.5) K31(13.5,7.5) K32(14.5,7.5) K33(15.5,7.5) K34(16.5,7.5) L1(-16.5,6.5) L2(-15.5,6.5) L3(-14.5,6.5) L4(-13.5,6.5) L5(-12.5,6.5) L6(-11.5,6.5) L7(-10.5,6.5) L8(-9.5,6.5) L9(-8.5,6.5) L10(-7.5,6.5) L11(-6.5,6.5) L12(-5.5,6.5) L13(-4.5,6.5) L14(-3.5,6.5) L15(-2.5,6.5) L16(-1.5,6.5) L17(-0.5,6.5) L18(0.5,6.5) L19(1.5,6.5) L20(2.5,6.5) L21(3.5,6.5) L22(4.5,6.5) L23(5.5,6.5) L24(6.5,6.5) L25(7.5,6.5) L26(8.5,6.5) L27(9.5,6.5) L28(10.5,6.5) L29(11.5,6.5) L30(12.5,6.5) L31(13.5,6.5) L32(14.5,6.5) L33(15.5,6.5) L34(16.5,6.5) M1(-16.5,5.5) M2(-15.5,5.5) M3(-14.5,5.5) M4(-13.5,5.5) M5(-12.5,5.5) M6(-11.5,5.5) M7(-10.5,5.5) M8(-9.5,5.5) M9(-8.5,5.5) M10(-7.5,5.5) M11(-6.5,5.5) M12(-5.5,5.5) M13(-4.5,5.5) M14(-3.5,5.5) M15(-2.5,5.5) M16(-1.5,5.5) M17(-0.5,5.5) M18(0.5,5.5) M19(1.5,5.5) M20(2.5,5.5) M21(3.5,5.5) M22(4.5,5.5) M23(5.5,5.5) M24(6.5,5.5) M25(7.5,5.5) M26(8.5,5.5) M27(9.5,5.5) M28(10.5,5.5) M29(11.5,5.5) M30(12.5,5.5) M31(13.5,5.5) M32(14.5,5.5) M33(15.5,5.5) M34(16.5,5.5) N1(-16.5,4.5) N2(-15.5,4.5) N3(-14.5,4.5) N4(-13.5,4.5) N5(-12.5,4.5) N6(-11.5,4.5) N7(-10.5,4.5) N8(-9.5,4.5) N9(-8.5,4.5) N10(-7.5,4.5) N11(-6.5,4.5) N12(-5.5,4.5) N13(-4.5,4.5) N14(-3.5,4.5) N15(-2.5,4.5) N16(-1.5,4.5) N17(-0.5,4.5) N18(0.5,4.5) N19(1.5,4.5) N20(2.5,4.5) N21(3.5,4.5) N22(4.5,4.5) N23(5.5,4.5) N24(6.5,4.5) N25(7.5,4.5) N26(8.5,4.5) N27(9.5,4.5) N28(10.5,4.5) N29(11.5,4.5) N30(12.5,4.5) N31(13.5,4.5) N32(14.5,4.5) N33(15.5,4.5) N34(16.5,4.5) P1(-16.5,3.5) P2(-15.5,3.5) P3(-14.5,3.5) P4(-13.5,3.5) P5(-12.5,3.5) P6(-11.5,3.5) P7(-10.5,3.5) P8(-9.5,3.5) P9(-8.5,3.5) P10(-7.5,3.5) P11(-6.5,3.5) P12(-5.5,3.5) P13(-4.5,3.5) P14(-3.5,3.5) P15(-2.5,3.5) P16(-1.5,3.5) P17(-0.5,3.5) P18(0.5,3.5) P19(1.5,3.5) P20(2.5,3.5) P21(3.5,3.5) P22(4.5,3.5) P23(5.5,3.5) P24(6.5,3.5) P25(7.5,3.5) P26(8.5,3.5) P27(9.5,3.5) P28(10.5,3.5) P29(11.5,3.5) P30(12.5,3.5) P31(13.5,3.5) P32(14.5,3.5) P33(15.5,3.5) P34(16.5,3.5) R1(-16.5,2.5) R2(-15.5,2.5) R3(-14.5,2.5) R4(-13.5,2.5) R5(-12.5,2.5) R6(-11.5,2.5) R7(-10.5,2.5) R8(-9.5,2.5) R9(-8.5,2.5) R10(-7.5,2.5) R11(-6.5,2.5) R12(-5.5,2.5) R13(-4.5,2.5) R14(-3.5,2.5) R15(-2.5,2.5) R16(-1.5,2.5) R17(-0.5,2.5) R18(0.5,2.5) R19(1.5,2.5) R20(2.5,2.5) R21(3.5,2.5) R22(4.5,2.5) R23(5.5,2.5) R24(6.5,2.5) R25(7.5,2.5) R26(8.5,2.5) R27(9.5,2.5) R28(10.5,2.5) R29(11.5,2.5) R30(12.5,2.5) R31(13.5,2.5) R32(14.5,2.5) R33(15.5,2.5) R34(16.5,2.5) T1(-16.5,1.5) T2(-15.5,1.5) T3(-14.5,1.5) T4(-13.5,1.5) T5(-12.5,1.5) T6(-11.5,1.5) T7(-10.5,1.5) T8(-9.5,1.5) T9(-8.5,1.5) T10(-7.5,1.5) T11(-6.5,1.5) T12(-5.5,1.5) T13(-4.5,1.5) T14(-3.5,1.5) T15(-2.5,1.5) T16(-1.5,1.5) T17(-0.5,1.5) T18(0.5,1.5) T19(1.5,1.5) T20(2.5,1.5) T21(3.5,1.5) T22(4.5,1.5) T23(5.5,1.5) T24(6.5,1.5) T25(7.5,1.5) T26(8.5,1.5) T27(9.5,1.5) T28(10.5,1.5) T29(11.5,1.5) T30(12.5,1.5) T31(13.5,1.5) T32(14.5,1.5) T33(15.5,1.5) T34(16.5,1.5) U1(-16.5,0.5) U2(-15.5,0.5) U3(-14.5,0.5) U4(-13.5,0.5) U5(-12.5,0.5) U6(-11.5,0.5) U7(-10.5,0.5) U8(-9.5,0.5) U9(-8.5,0.5) U10(-7.5,0.5) U11(-6.5,0.5) U12(-5.5,0.5) U13(-4.5,0.5) U14(-3.5,0.5) U15(-2.5,0.5) U16(-1.5,0.5) U17(-0.5,0.5) U18(0.5,0.5) U19(1.5,0.5) U20(2.5,0.5) U21(3.5,0.5) U22(4.5,0.5) U23(5.5,0.5) U24(6.5,0.5) U25(7.5,0.5) U26(8.5,0.5) U27(9.5,0.5) U28(10.5,0.5) U29(11.5,0.5) U30(12.5,0.5) U31(13.5,0.5) U32(14.5,0.5) U33(15.5,0.5) U34(16.5,0.5) V1(-16.5,-0.5) V2(-15.5,-0.5) V3(-14.5,-0.5) V4(-13.5,-0.5) V5(-12.5,-0.5) V6(-11.5,-0.5) V7(-10.5,-0.5) V8(-9.5,-0.5) V9(-8.5,-0.5) V10(-7.5,-0.5) V11(-6.5,-0.5) V12(-5.5,-0.5) V13(-4.5,-0.5) V14(-3.5,-0.5) V15(-2.5,-0.5) V16(-1.5,-0.5) V17(-0.5,-0.5) V18(0.5,-0.5) V19(1.5,-0.5) V20(2.5,-0.5) V21(3.5,-0.5) V22(4.5,-0.5) V23(5.5,-0.5) V24(6.5,-0.5) V25(7.5,-0.5) V26(8.5,-0.5) V27(9.5,-0.5) V28(10.5,-0.5) V29(11.5,-0.5) V30(12.5,-0.5) V31(13.5,-0.5) V32(14.5,-0.5) V33(15.5,-0.5) V34(16.5,-0.5) W1(-16.5,-1.5) W2(-15.5,-1.5) W3(-14.5,-1.5) W4(-13.5,-1.5) W5(-12.5,-1.5) W6(-11.5,-1.5) W7(-10.5,-1.5) W8(-9.5,-1.5) W9(-8.5,-1.5) W10(-7.5,-1.5) W11(-6.5,-1.5) W12(-5.5,-1.5) W13(-4.5,-1.5) W14(-3.5,-1.5) W15(-2.5,-1.5) W16(-1.5,-1.5) W17(-0.5,-1.5) W18(0.5,-1.5) W19(1.5,-1.5) W20(2.5,-1.5) W21(3.5,-1.5) W22(4.5,-1.5) W23(5.5,-1.5) W24(6.5,-1.5) W25(7.5,-1.5) W26(8.5,-1.5) W27(9.5,-1.5) W28(10.5,-1.5) W29(11.5,-1.5) W30(12.5,-1.5) W31(13.5,-1.5) W32(14.5,-1.5) W33(15.5,-1.5) W34(16.5,-1.5) Y1(-16.5,-2.5) Y2(-15.5,-2.5) Y3(-14.5,-2.5) Y4(-13.5,-2.5) Y5(-12.5,-2.5) Y6(-11.5,-2.5) Y7(-10.5,-2.5) Y8(-9.5,-2.5) Y9(-8.5,-2.5) Y10(-7.5,-2.5) Y11(-6.5,-2.5) Y12(-5.5,-2.5) Y13(-4.5,-2.5) Y14(-3.5,-2.5) Y15(-2.5,-2.5) Y16(-1.5,-2.5) Y17(-0.5,-2.5) Y18(0.5,-2.5) Y19(1.5,-2.5) Y20(2.5,-2.5) Y21(3.5,-2.5) Y22(4.5,-2.5) Y23(5.5,-2.5) Y24(6.5,-2.5) Y25(7.5,-2.5) Y26(8.5,-2.5) Y27(9.5,-2.5) Y28(10.5,-2.5) Y29(11.5,-2.5) Y30(12.5,-2.5) Y31(13.5,-2.5) Y32(14.5,-2.5) Y33(15.5,-2.5) Y34(16.5,-2.5)
C0402
  custom 0.138x0.138 smd: 1(-0.525,0) 2(0.525,0)
C0402-8
  custom 0.127x0.127 smd: 1(-0.508,0) 2(0.508,0)
C0603
  rect 0.914x0.914 smd: 1(-0.813,0) 2(0.813,0)
C0805
  custom 0.2x0.2 smd: 1(-0.95,0) 2(0.95,0)
CAP196_POL_3_5MM
  rect 1.524x1.524 hole 0.914: 1(-1.75,0)
  round 1.524 hole 0.914: 2(1.75,0)
CON2
  rect 1.524x1.524 hole 0.914: 1(-1.27,0)
  round 1.524 hole 0.914: 2(1.27,0)
CONN1X2_2_54
  rect 1.524x1.524 hole 0.914: 1(0,0)
  round 1.524 hole 0.914: 2(2.54,0)
CONN1X4_2_54
  rect 1.524x1.524 hole 0.914: 1(0,0)
  round 1.524 hole 0.914: 2(2.54,0) 3(5.08,0) 4(7.62,0)
CONN7
  rect 1.524x1.524 hole 0.914: 1(0,0)
  round 1.524 hole 0.914: 2(0,2.54) 3(2.54,0) 4(2.54,2.54) 5(5.08,0) 6(5.08,2.54) 7(7.62,2.54)
CONN10
  rect 1.524x1.524 hole 0.914: 1(0,0)
  round 1.524 hole 0.914: 2(0,2.54) 3(2.54,0) 4(2.54,2.54) 5(5.08,0) 6(5.08,2.54) 7(7.62,0) 8(7.62,2.54) 9(10.16,0) 10(10.16,2.54)
DQP_N22
  rect 0.813x0.254 smd: 1(-2.475,2.5) 2(-2.475,2) 3(-2.475,1.5) 4(-2.475,1) 5(-2.475,0.5) 6(-2.475,0) 7(-2.475,-0.5) 8(-2.475,-1) 9(-2.475,-1.5) 10(-2.475,-2) 11(-2.475,-2.5) 12(2.475,-2.5) 13(2.475,-2) 14(2.475,-1.5) 15(2.475,-1) 16(2.475,-0.5) 17(2.475,0) 18(2.475,0.5) 19(2.475,1) 20(2.475,1.5) 21(2.475,2) 22(2.475,2.5)
  rect 3.251x5.486 smd: 23(0,0)
DRILL_1X4_3_96
  round 3.108 hole 2.032: 1(0,0) 2(3.96,0) 3(7.92,0) 4(11.88,0)
DS125MB203
  rect 0.6x0.25 smd: 1(-2.65,4.25) 2(-2.65,3.75) 3(-2.65,3.25) 4(-2.65,2.75) 5(-2.65,2.25) 6(-2.65,1.75) 7(-2.65,1.25) 8(-2.65,0.75) 9(-2.65,0.25) 10(-2.65,-0.25) 11(-2.65,-0.75) 12(-2.65,-1.25) 13(-2.65,-1.75) 14(-2.65,-2.25) 15(-2.65,-2.75) 16(-2.65,-3.25) 17(-2.65,-3.75) 18(-2.65,-4.25) 28(2.65,-4.25) 29(2.65,-3.75) 30(2.65,-3.25) 31(2.65,-2.75) 32(2.65,-2.25) 33(2.65,-1.75) 34(2.65,-1.25) 35(2.65,-0.75) 36(2.65,-0.25) 37(2.65,0.25) 38(2.65,0.75) 39(2.65,1.25) 40(2.65,1.75) 41(2.65,2.25) 42(2.65,2.75) 43(2.65,3.25) 44(2.65,3.75) 45(2.65,4.25)
  rect 0.25x0.6 smd: 19(-2,-4.9) 20(-1.5,-4.9) 21(-1,-4.9) 22(-0.5,-4.9) 23(0,-4.9) 24(0.5,-4.9) 25(1,-4.9) 26(1.5,-4.9) 27(2,-4.9) 46(2,4.9) 47(1.5,4.9) 48(1,4.9) 49(0.5,4.9) 50(0,4.9) 51(-0.5,4.9) 52(-1,4.9) 53(-1.5,4.9) 54(-2,4.9)
  rect 3.51x7.5 smd: 55(0,0)
ERNI_973046
  round 0.813 hole 0.61: A1(11.25,-3.75) A2(8.75,-3.75) A3(6.25,-3.75) A4(3.75,-3.75) A5(1.25,-3.75) A6(-1.25,-3.75) A7(-3.75,-3.75) A8(-6.25,-3.75) A9(-8.75,-3.75) A10(-11.25,-3.75) AB1(11.25,-0.75) AB2(8.75,-0.75) AB3(6.25,-0.75) AB4(3.75,-0.75) AB5(1.25,-0.75) AB6(-1.25,-0.75) AB7(-3.75,-0.75) AB8(-6.25,-0.75) AB9(-8.75,-0.75) AB10(-11.25,-0.75) B1(11.25,-2.25) B2(8.75,-2.25) B3(6.25,-2.25) B4(3.75,-2.25) B5(1.25,-2.25) B6(-1.25,-2.25) B7(-3.75,-2.25) B8(-6.25,-2.25) B9(-8.75,-2.25) B10(-11.25,-2.25) C1(11.25,0.75) C2(8.75,0.75) C3(6.25,0.75) C4(3.75,0.75) C5(1.25,0.75) C6(-1.25,0.75) C7(-3.75,0.75) C8(-6.25,0.75) C9(-8.75,0.75) C10(-11.25,0.75) CD1(11.25,3.75) CD2(8.75,3.75) CD3(6.25,3.75) CD4(3.75,3.75) CD5(1.25,3.75) CD6(-1.25,3.75) CD7(-3.75,3.75) CD8(-6.25,3.75) CD9(-8.75,3.75) CD10(-11.25,3.75) D1(11.25,2.25) D2(8.75,2.25) D3(6.25,2.25) D4(3.75,2.25) D5(1.25,2.25) D6(-1.25,2.25) D7(-3.75,2.25) D8(-6.25,2.25) D9(-8.75,2.25) D10(-11.25,2.25)
FBGA96-10X14
  round 0.406 smd: A1(-3.2,6) A2(-2.4,6) A3(-1.6,6) A7(1.6,6) A8(2.4,6) A9(3.2,6) B1(-3.2,5.2) B2(-2.4,5.2) B3(-1.6,5.2) B7(1.6,5.2) B8(2.4,5.2) B9(3.2,5.2) C1(-3.2,4.4) C2(-2.4,4.4) C3(-1.6,4.4) C7(1.6,4.4) C8(2.4,4.4) C9(3.2,4.4) D1(-3.2,3.6) D2(-2.4,3.6) D3(-1.6,3.6) D7(1.6,3.6) D8(2.4,3.6) D9(3.2,3.6) E1(-3.2,2.8) E2(-2.4,2.8) E3(-1.6,2.8) E7(1.6,2.8) E8(2.4,2.8) E9(3.2,2.8) F1(-3.2,2) F2(-2.4,2) F3(-1.6,2) F7(1.6,2) F8(2.4,2) F9(3.2,2) G1(-3.2,1.2) G2(-2.4,1.2) G3(-1.6,1.2) G7(1.6,1.2) G8(2.4,1.2) G9(3.2,1.2) H1(-3.2,0.4) H2(-2.4,0.4) H3(-1.6,0.4) H7(1.6,0.4) H8(2.4,0.4) H9(3.2,0.4) J1(-3.2,-0.4) J2(-2.4,-0.4) J3(-1.6,-0.4) J7(1.6,-0.4) J8(2.4,-0.4) J9(3.2,-0.4) K1(-3.2,-1.2) K2(-2.4,-1.2) K3(-1.6,-1.2) K7(1.6,-1.2) K8(2.4,-1.2) K9(3.2,-1.2) L1(-3.2,-2) L2(-2.4,-2) L3(-1.6,-2) L7(1.6,-2) L8(2.4,-2) L9(3.2,-2) M1(-3.2,-2.8) M2(-2.4,-2.8) M3(-1.6,-2.8) M7(1.6,-2.8) M8(2.4,-2.8) M9(3.2,-2.8) N1(-3.2,-3.6) N2(-2.4,-3.6) N3(-1.6,-3.6) N7(1.6,-3.6) N8(2.4,-3.6) N9(3.2,-3.6) P1(-3.2,-4.4) P2(-2.4,-4.4) P3(-1.6,-4.4) P7(1.6,-4.4) P8(2.4,-4.4) P9(3.2,-4.4) R1(-3.2,-5.2) R2(-2.4,-5.2) R3(-1.6,-5.2) R7(1.6,-5.2) R8(2.4,-5.2) R9(3.2,-5.2) T1(-3.2,-6) T2(-2.4,-6) T3(-1.6,-6) T7(1.6,-6) T8(2.4,-6) T9(3.2,-6)
HDMI
  rect 0.3x3 smd: 1(4.5,0) 2(4,0) 3(3.5,0) 4(3,0) 5(2.5,0) 6(2,0) 7(1.5,0) 8(1,0) 9(0.5,0) 10(0,0) 11(-0.5,0) 12(-1,0) 13(-1.5,0) 14(-2,0) 15(-2.5,0) 16(-3,0) 17(-3.5,0) 18(-4,0) 19(-4.5,0)
  oval 1.5x3.3 hole 0.9x2.7: MTG1(-7.25,-1) MTG2(7.25,-1)
  oval 1.5x2.3 hole 0.9x1.7: MTG3(-7.25,-6.84) MTG4(7.25,-6.84)
ID-BOARD
  round 1.016 smd: 1(0,0)
IND4X4
  rect 1.5x4 smd: 1(-1.5,0) 2(1.5,0)
L_GFB_58X28
  rect 3.048x5.08 smd: 1(-2.508,0) 2(2.508,0)
LED-4P
  rect 1.524x1.524 hole 0.914: 1(-1.27,0)
  round 1.524 hole 0.914: 2(1.27,0) 3(-1.27,2.54) 4(1.27,2.54)
LQFP48
  rect 0.25x1.2 smd: 1(-2.75,-4.25) 2(-2.25,-4.25) 3(-1.75,-4.25) 4(-1.25,-4.25) 5(-0.75,-4.25) 6(-0.25,-4.25) 7(0.25,-4.25) 8(0.75,-4.25) 9(1.25,-4.25) 10(1.75,-4.25) 11(2.25,-4.25) 12(2.75,-4.25) 25(2.75,4.25) 26(2.25,4.25) 27(1.75,4.25) 28(1.25,4.25) 29(0.75,4.25) 30(0.25,4.25) 31(-0.25,4.25) 32(-0.75,4.25) 33(-1.25,4.25) 34(-1.75,4.25) 35(-2.25,4.25) 36(-2.75,4.25)
  rect 1.2x0.25 smd: 13(4.25,-2.75) 14(4.25,-2.25) 15(4.25,-1.75) 16(4.25,-1.25) 17(4.25,-0.75) 18(4.25,-0.25) 19(4.25,0.25) 20(4.25,0.75) 21(4.25,1.25) 22(4.25,1.75) 23(4.25,2.25) 24(4.25,2.75) 37(-4.25,2.75) 38(-4.25,2.25) 39(-4.25,1.75) 40(-4.25,1.25) 41(-4.25,0.75) 42(-4.25,0.25) 43(-4.25,-0.25) 44(-4.25,-0.75) 45(-4.25,-1.25) 46(-4.25,-1.75) 47(-4.25,-2.25) 48(-4.25,-2.75)
MY_0603_RES
  rect 1.016x0.762 smd: 1(-0.889,0) 2(0.889,0)
QFN24
  oval 0.813x0.279 smd: 1(-1.95,1.25) 2(-1.95,0.75) 3(-1.95,0.25) 4(-1.95,-0.25) 5(-1.95,-0.75) 6(-1.95,-1.25) 13(1.95,-1.25) 14(1.95,-0.75) 15(1.95,-0.25) 16(1.95,0.25) 17(1.95,0.75) 18(1.95,1.25)
  oval 0.279x0.813 smd: 7(-1.25,-1.95) 8(-0.75,-1.95) 9(-0.25,-1.95) 10(0.25,-1.95) 11(0.75,-1.95) 12(1.25,-1.95) 19(1.25,1.95) 20(0.75,1.95) 21(0.25,1.95) 22(-0.25,1.95) 23(-0.75,1.95) 24(-1.25,1.95)
  rect 2.591x2.591 smd: 25(0,0)
QFN48_TMDS181
  oval 1x0.24 smd: 1(-3.6,2.75) 2(-3.6,2.25) 3(-3.6,1.75) 4(-3.6,1.25) 5(-3.6,0.75) 6(-3.6,0.25) 7(-3.6,-0.25) 8(-3.6,-0.75) 9(-3.6,-1.25) 10(-3.6,-1.75) 11(-3.6,-2.25) 12(-3.6,-2.75) 25(3.6,-2.75) 26(3.6,-2.25) 27(3.6,-1.75) 28(3.6,-1.25) 29(3.6,-0.75) 30(3.6,-0.25) 31(3.6,0.25) 32(3.6,0.75) 33(3.6,1.25) 34(3.6,1.75) 35(3.6,2.25) 36(3.6,2.75)
  oval 0.24x1 smd: 13(-2.75,-3.6) 14(-2.25,-3.6) 15(-1.75,-3.6) 16(-1.25,-3.6) 17(-0.75,-3.6) 18(-0.25,-3.6) 19(0.25,-3.6) 20(0.75,-3.6) 21(1.25,-3.6) 22(1.75,-3.6) 23(2.25,-3.6) 24(2.75,-3.6) 37(2.75,3.6) 38(2.25,3.6) 39(1.75,3.6) 40(1.25,3.6) 41(0.75,3.6) 42(0.25,3.6) 43(-0.25,3.6) 44(-0.75,3.6) 45(-1.25,3.6) 46(-1.75,3.6) 47(-2.25,3.6) 48(-2.75,3.6)
  rect 4.1x4.1 smd: 49(0,0)
R0402
  custom 0.15x0.15 smd: 1(-0.562,0) 2(0.562,0)
R0603
  rect 0.65x0.8 smd: 1(-0.725,0) 2(0.725,0)
R0805
  rect 1.143x1.524 smd: 1(-1.079,0) 2(1.079,0)
SMA_DIODES
  rect 1.5x2 smd: 1(0.25,0) 2(4.25,0)
SOIC8_E0D65_4D55XE3D15
  oval 1.016x0.305 smd: 1(-2.125,0.975) 2(-2.125,0.325) 3(-2.125,-0.325) 4(-2.125,-0.975) 5(2.125,-0.975) 6(2.125,-0.325) 7(2.125,0.325) 8(2.125,0.975)
SOIC8W
  rect 1.27x0.635 smd: 1(0,0) 2(0,-1.27) 3(0,-2.54) 4(0,-3.81) 5(7.899,-3.81) 6(7.899,-2.54) 7(7.899,-1.27) 8(7.899,0)
SOT23-5
  rect 0.6x1.2 smd: 1(-0.95,-1.1) 2(0,-1.1) 3(0.95,-1.1) 4(0.95,1.1) 5(-0.95,1.1)
SOT-23
  rect 0.813x1.143 smd: 1(-0.953,-1.029) 2(0.953,-1.029) 3(0,1.029)
SOT_23_5
  oval 1.1x0.6 smd: 1(-1.4,1)
  rect 1.1x0.6 smd: 2(-1.4,0) 3(-1.4,-1) 4(1.4,-1) 5(1.4,1)
T-PBGA24-BALL
  round 0.406 smd: A2(-1,2) A3(0,2) A4(1,2) A5(2,2) B1(-2,1) B2(-1,1) B3(0,1) B4(1,1) B5(2,1) C1(-2,0) C2(-1,0) C3(0,0) C4(1,0) C5(2,0) D1(-2,-1) D2(-1,-1) D3(0,-1) D4(1,-1) D5(2,-1) E1(-2,-2) E2(-1,-2) E3(0,-2) E4(1,-2) E5(2,-2)
TOOL_1H_8D_C_LC_02
  round 1.016 hole 0.813: 1(0,3.734) 2(2.64,2.64) 3(3.734,0) 4(2.64,-2.64) 5(0,-3.734) 6(-2.64,-2.64) 7(-3.734,0) 8(-2.64,2.64)
  round 9.855 hole 3.962: 9(0,0)
TPS51200
  rect 0.28x0.85 smd: 1(-1,-1.475) 2(-0.5,-1.475) 3(0,-1.475) 4(0.5,-1.475) 5(1,-1.475) 6(1,1.475) 7(0.5,1.475) 8(0,1.475) 9(-0.5,1.475) 10(-1,1.475)
  rect 2.4x1.65 smd: 11(0,0)
TPS568215
  rect 0.61x0.254 smd: 1(-1.65,0.925) 12(1.65,0.925)
  rect 1.168x0.406 smd: 2(-1.375,0.35) 11(1.375,0.35)
  rect 1.168x0.254 smd: 3(-1.375,-0.3) 4(-1.375,-0.85) 5(-1.375,-1.4) 8(1.375,-1.4) 9(1.375,-0.85) 10(1.375,-0.3)
  rect 0.305x2.642 smd: 6(-0.3,-0.65) 7(0.3,-0.65)
  rect 0.254x0.61 smd: 13(1.25,1.65) 14(0.75,1.65) 15(0.25,1.65) 16(-0.25,1.65) 17(-0.75,1.65) 18(-1.25,1.65)
UDFN-10
  rect 0.2x0.675 smd: 1(0,0) 2(0.5,0) 4(1.5,0) 5(2,0) 6(2,0.875) 7(1.5,0.875) 9(0.5,0.875) 10(0,0.875)
  rect 0.4x0.675 smd: 3(1,0) 8(1,0.875)
unnamed
  round 3.099 hole 3.099 unplated: (-20.86,-20.86) (20.86,20.86)
unnamed#3
  round 1.016 smd: 1(0,0)
XTAL_ABM8
  rect 1.321x1.041 smd: 1(-1.156,-0.94) 2(1.156,-0.94) 3(1.156,0.94) 4(-1.156,0.94)

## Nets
D0V9_EN: R245.2 U43.31(PA10) U56.2(EN)
D0V9_VFB: C334.1 R283.1 R291.2 U56.1(VFB)
D0V9_VREG: C386.1 R488.1 R493.2 U56.18(VREG)
D1V0_EN: R247.2 U43.32(PA11) U53.15(EN)
D1V0_VREG: C377.1 R319.2 R323.1 U53.17(VREG5)
D1V2: C317.1 C318.1 C319.1 C320.1 C321.1 C383.1 L13.2 L17.2 L19.2 L22.2 L24.2 R305.2
D1V2_OUT1: C406.2 C407.2 C408.2 C409.2 C411.2 C412.2 C414.2 C415.2 L17.1 U19.14(VDD1) U19.23(VDD2) U19.24(VDD3) U19.37(VDD4) U19.48(VDD5)
D1V2_OUT2: C538.2 C539.2 C540.2 C541.2 C586.2 C587.2 C589.2 C590.2 L19.1 U29.14(VDD1) U29.23(VDD2) U29.24(VDD3) U29.37(VDD4) U29.48(VDD5)
D1V2_OUT3: C600.2 C601.2 C602.2 C603.2 C604.2 C605.2 C607.2 C608.2 L22.1 U37.14(VDD1) U37.23(VDD2) U37.24(VDD3) U37.37(VDD4) U37.48(VDD5)
D1V2_OUT4: C618.2 C619.2 C620.2 C621.2 C627.2 C628.2 C630.2 C631.2 L24.1 U48.14(VDD1) U48.23(VDD2) U48.24(VDD3) U48.37(VDD4) U48.48(VDD5)
D1V2_VREG: C374.1 R318.2 R322.1 U52.17(VREG5)
D1V5_VREG: C56.1 R45.2 R46.1 U9.17(VREG5)
D1V8: C283.1 C286.1 C287.1 L5.2 L6.2 L7.2 R272.2
D1V8_EN: R238.2 U43.29(PA8) U54.15(EN)
D1V8_VREG: C380.1 R320.2 R324.1 U54.17(VREG5)
D3V3: C22.1 C95.1 C145.1 C155.1 C157.1 C162.1 C173.1 C190.1 C192.1 C197.1 C200.1 C204.1 C230.1 C265.1 C267.1 C268.1 C280.1 C337.1 C363.1 C609.1 C610.1 C612.1 C613.1 L1.1 L4.2 L16.2 L18.2 L21.2 L23.2 R19.2 R22.2 R61.2 R62.2 R133.1 R151.2 R197.2 R198.2 R216.2 R224.2 R225.1 R246.1 R249.2 R250.2 R255.2 R256.2 R474.1 U5.10(VIN) U14.10(VIN) U26.7(VDD1) U26.24(VDD2) U34.10(VIN) U38.3(VCC0) U38.7(VCC2) U38.8(VCC1) U39.7(VDD1) U39.24(VDD2) U43.1(VBAT) U43.9(VDDA) U43.24(VDD) U43.48(VDDD) U50.4(VIN) Y1.4(VCC) Y3.4(VCC)
D3V3_HM21: C8.2 C13.2 C44.2 C45.2 C46.2 C49.2 C704.2 L1.2 R16.1 R17.1 R18.1 R20.1 R21.1 R24.1 R25.1 R39.1 R335.2 R337.2 R338.2 R341.2 R343.2 R344.2 R347.2 R349.2 R350.2 R367.2 R368.2 R371.2 R373.2 U59.24(VIN)
D3V3_OUT1: C402.2 C403.2 C404.2 C405.2 C413.2 L16.1 R57.2 R66.1 R69.1 R71.1 R72.1 R74.1 R80.1 R82.1 R83.1 R84.1 R85.1 R86.1 R87.1 R88.1 R381.1 R384.1 R391.1 R393.1 U19.13(VCC1) U19.43(VCC2)
D3V3_OUT2: C510.2 C511.2 C536.2 C537.2 C588.2 L18.1 R115.2 R123.1 R126.1 R128.1 R129.1 R131.1 R142.1 R144.1 R146.1 R149.1 R150.1 R153.1 R155.1 R158.1 R436.1 R441.1 R452.1 R455.1 U29.13(VCC1) U29.43(VCC2)
D3V3_OUT3: C596.2 C597.2 C598.2 C599.2 C606.2 L21.1 R177.2 R200.1 R203.1 R205.1 R206.1 R208.1 R213.1 R214.1 R215.1 R217.1 R218.1 R219.1 R220.1 R223.1 R462.1 R465.1 R471.1 R473.1 U37.13(VCC1) U37.43(VCC2)
D3V3_OUT4: C614.2 C615.2 C616.2 C617.2 C629.2 L23.1 R252.2 R262.1 R265.1 R267.1 R268.1 R270.1 R275.1 R276.1 R277.1 R278.1 R279.1 R280.1 R281.1 R282.1 R475.1 R478.1 R485.1 R487.1 U48.13(VCC1) U48.43(VCC2)
D3V3_VREG: C177.1 R136.2 R140.1 U25.17(VREG5)
D5V: C59.2 C146.2 C226.2 C285.2 C288.1 C289.1 C303.1 C312.1 C313.1 C314.1 C315.1 C316.1 C382.1 D1.2(A) D2.2(A) D3.2(A) D4.2(A) L12.2 R6.1 R8.1 R13.2 R100.2 R101.2 R102.2 R104.2 R110.2 R167.2 R169.2 R170.2 R171.2 R175.2 R236.2 R239.2 R240.2 R241.2 R248.2 R260.1 R296.2 R297.2 R298.2 R299.2 R303.2 R304.2 U13.5(IN) U23.5(IN) U33.5(IN) U44.5(IN) U45.4(VIN)
D5V_OUT1: C106.1 D1.1(K) R63.2 U13.1(VOUT)
D5V_OUT2: C163.1 D2.1(K) R120.2 U23.1(VOUT)
D5V_OUT3: C229.1 D3.1(K) R196.2 U33.1(VOUT)
D5V_OUT4: C294.1 D4.1(K) R258.2 U44.1(VOUT)
D5V_VREG: C371.1 R317.2 R321.1 U51.17(VREG5)
D12V: C29.1 C33.1 C36.1 C60.1 C76.1 C89.1 C148.1 C156.1 C158.1 C171.1 C179.1 C188.1 C193.1 C201.1 C211.1 C227.1 C339.1 C340.1 C341.1 C342.1 C343.1 C344.1 C345.1 C346.1 C347.1 C348.1 C349.1 C350.1 C351.1 C352.1 C353.1 C354.1 C355.1 C356.1 C357.1 C358.1 C359.1 C360.1 C361.1 C362.1 C365.1 C366.1 C367.1 C368.1 C369.1 C632.1 FAN1.1 FAN2.1 J13.3 J13.4 J15.1 JA1.1 JA1.2 JT1.A1(D-C1) JT1.A2(D-C2) JT1.A3(D-C3) JT1.B1(D-D1) JT1.B2(D-D2) JT1.B3(D-D3) R1.1 U9.2(VIN1) U9.11(VIN2) U25.2(VIN1) U25.11(VIN2) U51.2(VIN1) U51.11(VIN2) U52.2(VIN1) U52.11(VIN2) U53.2(VIN1) U53.11(VIN2) U54.2(VIN1) U54.11(VIN2) U56.12(VIN#12) U56.13(VIN#13) U56.14(VIN#14) U56.15(VIN#15) U56.16(VIN#16) U56.17(VIN#17) U56.19(VDD)
